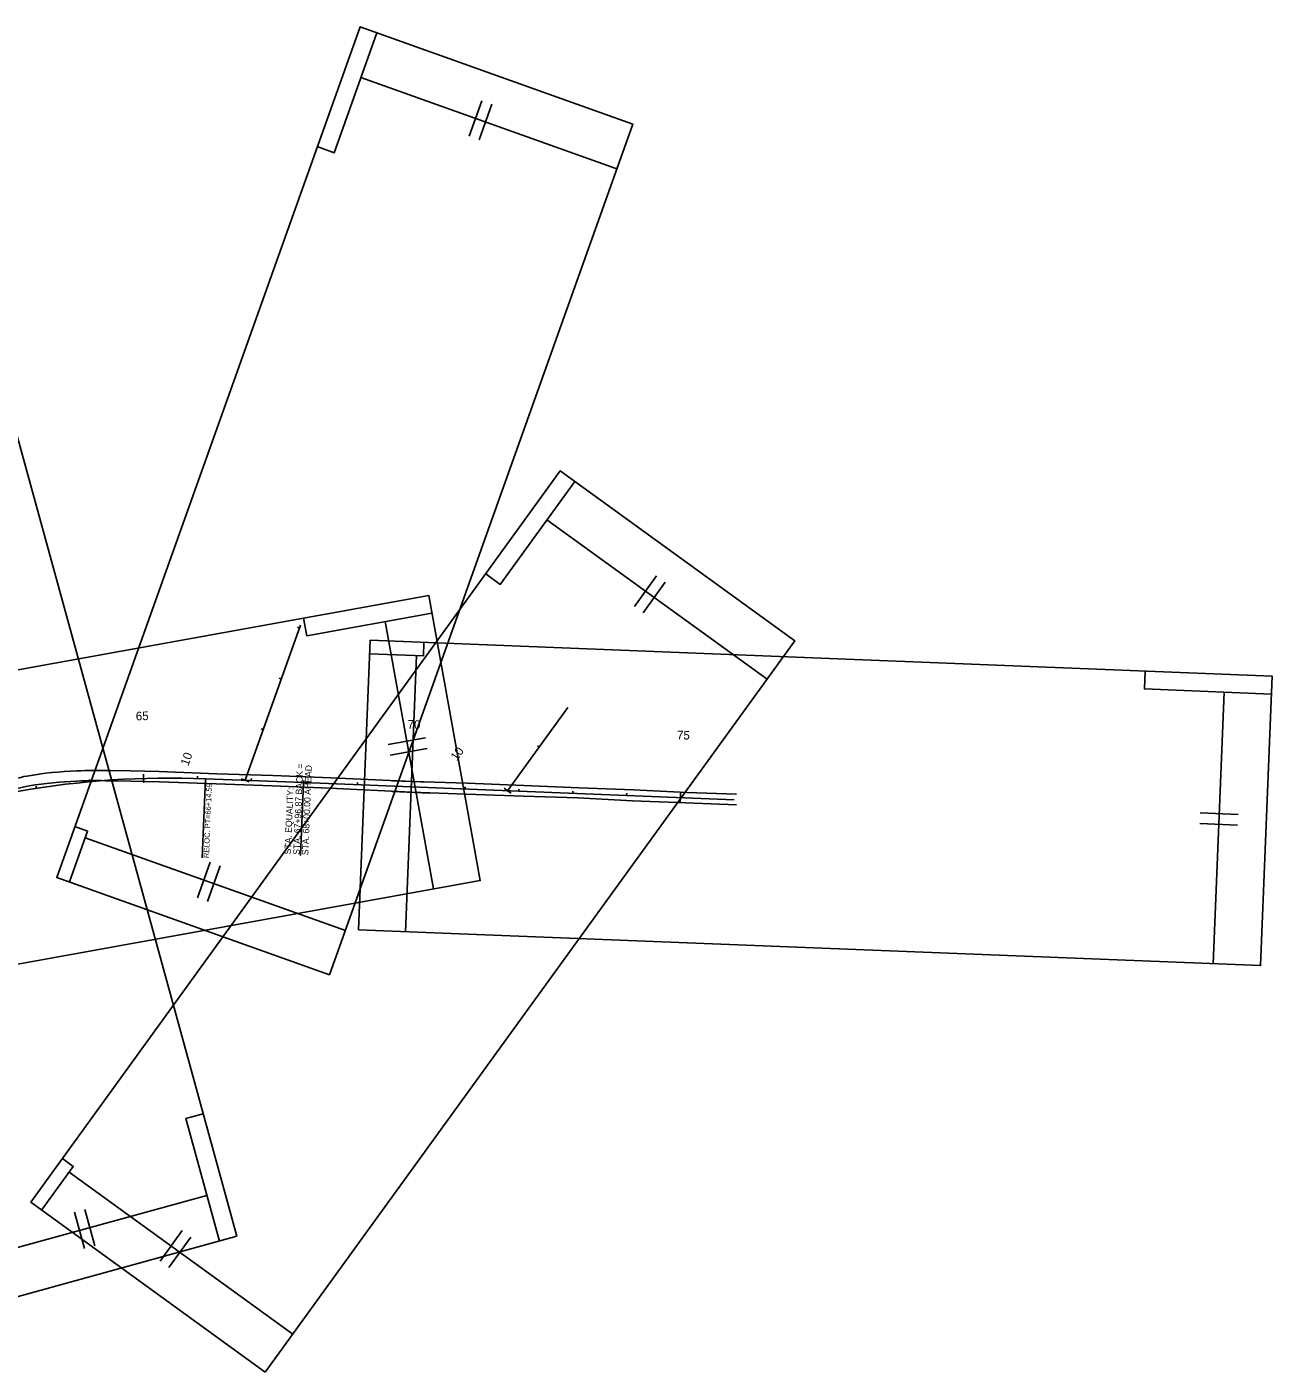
# Model space of a CAD drawing. Extents: x 1965658 to 1970277, y 1116791 to 1119319.
# Drawn here: x 1967966 to 1970277, y 1116823 to 1119319 of the extents above; entities that cross this region are included whole.
import ezdxf

# ---------------------------------------------------------------- set-up
doc = ezdxf.new("R2010")
doc.units = 0
for name, color, linetype in [('RD_EX_Road', 7, 'Continuous'), ('RD_HC_CL', 7, 'Continuous'), ('RD_HC_CL_Rel', 7, 'Continuous'), ('RD_HC_Data_Rel', 7, 'Continuous'), ('RD_HC_Data_Tic', 7, 'Continuous'), ('RD_HC_Data_Tic_Rel', 7, 'Continuous'), ('RD_HC_TX_Rel_Sta50', 7, 'Continuous'), ('RD_HC_TX_Sta50', 7, 'Continuous'), ('RD_SHT_Bndy', 7, 'Continuous')]:
    doc.layers.add(name, color=color, linetype=linetype)

msp = doc.modelspace()

# ---------------------------------------------------------------- linework, layer by layer
at = {"layer": 'RD_EX_Road'}
for points in [[(1968120.7, 1117939.2), (1968158.7, 1117938.6), (1968212.1, 1117937.2), (1968318.8, 1117933.3), (1968422.8, 1117929.9), (1968530.5, 1117925.7)], [(1968530.5, 1117925.7), (1968682, 1117919), (1968783.2, 1117915.4), (1968888.6, 1117911.4), (1968991.2, 1117907.1), (1969092, 1117903.1), (1969191.1, 1117898.7), (1969283.3, 1117895.4)], [(1968119.9, 1117920.1), (1968159.2, 1117919.4), (1968212.5, 1117918), (1968317.5, 1117914.4), (1968421.5, 1117910.8), (1968527.8, 1117906.4)], [(1968527.8, 1117906.4), (1968680.8, 1117899.1), (1968781.7, 1117895.4), (1968887.9, 1117891.8), (1968988.7, 1117888.2), (1969090.1, 1117882.8), (1969189.3, 1117879), (1969282.9, 1117875.4)]]:
    msp.add_lwpolyline(points, dxfattribs=at)
for centre, radius, start, end in [((1968104.9, 1117261.1), 682.1, 101.7162, 109.6396), ((1968075.1, 1117320.6), 617.9, 91.4965, 100.1295), ((1968100.4, 1117116.1), 823.4, 88.5878, 92.8836), ((1968081.5, 1117359.5), 562.4, 101.3634, 110.7161), ((1968080.7, 1117246.5), 673.3, 91.837, 99.4057), ((1968097.6, 1117060.1), 860.3, 88.5163, 92.5646)]:
    msp.add_arc(centre, radius, start, end, dxfattribs=at)
at = {"layer": 'RD_HC_CL'}
for p, q in [((1968371.4, 1117921), (1968474, 1118208.6)), ((1968858.2, 1117901.7), (1968970.1, 1118056.2))]:
    msp.add_line(p, q, dxfattribs=at)
at = {"layer": 'RD_HC_CL_Rel'}
for p, q in [((1968297.5, 1117923.9), (1968479.6, 1117916.7)), ((1968479.6, 1117916.7), (1969279, 1117884.9))]:
    msp.add_line(p, q, dxfattribs=at)
msp.add_arc((1968232.6, 1116288.2), 1637, 87.7266, 111.9958, dxfattribs=at)
at = {"layer": 'RD_HC_Data_Rel'}
for p, q in [((1968297.5, 1117923.9), (1968291.7, 1117777.2)), ((1968479.6, 1117916.7), (1968474.3, 1117781.6))]:
    msp.add_line(p, q, dxfattribs=at)
at = {"layer": 'RD_HC_Data_Tic'}
for p, q in [((1968472.1, 1118203.5), (1968468.4, 1118204.9)), ((1968438.5, 1118109.4), (1968434.8, 1118110.7)), ((1968404.9, 1118015.2), (1968401.2, 1118016.5)), ((1968916.8, 1117982.6), (1968913.6, 1117985)), ((1968371.4, 1117921), (1968363.8, 1117923.7)), ((1968371.4, 1117921), (1968378.9, 1117918.3)), ((1968858.2, 1117901.7), (1968851.7, 1117906.3)), ((1968858.2, 1117901.7), (1968864.7, 1117897))]:
    msp.add_line(p, q, dxfattribs=at)
at = {"layer": 'RD_HC_Data_Tic_Rel'}
for p, q in [((1968182.9, 1117924.4), (1968182.7, 1117932.4)), ((1968282.9, 1117924.4), (1968283, 1117928.4)), ((1967983.9, 1117906.2), (1967983.3, 1117910.2)), ((1968083.1, 1117918.4), (1968082.8, 1117922.3)), ((1968182.9, 1117924.4), (1968183.2, 1117916.5)), ((1968382.8, 1117920.5), (1968383, 1117924.5)), ((1968479.6, 1117916.7), (1968479.8, 1117920.7)), ((1968579.6, 1117912.7), (1968579.7, 1117916.7)), ((1968679.5, 1117908.7), (1968679.2, 1117900.8)), ((1968679.5, 1117908.7), (1968679.8, 1117916.7)), ((1968779.4, 1117904.8), (1968779.6, 1117908.8)), ((1968879.3, 1117900.8), (1968879.5, 1117904.8)), ((1968979.3, 1117896.8), (1968979.4, 1117900.8)), ((1969079.2, 1117892.9), (1969079.3, 1117896.9)), ((1969179.1, 1117888.9), (1969178.8, 1117880.9)), ((1969179.1, 1117888.9), (1969179.4, 1117896.9))]:
    msp.add_line(p, q, dxfattribs=at)
at = {"layer": 'RD_SHT_Bndy'}
for p, q in [((1969061.2, 1119055.1), (1968586.2, 1119224.6)), ((1968786.9, 1119115.8), (1968810.4, 1119181.7)), ((1968805.7, 1119109.1), (1968829.3, 1119175)), ((1969339.8, 1118108.4), (1968931.4, 1118404.3)), ((1969093.6, 1118243.6), (1969134.6, 1118300.3)), ((1969109.7, 1118231.9), (1969150.8, 1118288.5)), ((1968721.1, 1117719.4), (1968631.3, 1118215.7)), ((1968668.8, 1117640.2), (1968689.2, 1118152.3)), ((1970167.6, 1117580.7), (1970187.7, 1118084.6)), ((1968637, 1117987.5), (1968705.9, 1117999.9)), ((1968640.6, 1117967.8), (1968709.4, 1117980.3)), ((1968644.9, 1117920.1), (1968714.9, 1117917.4)), ((1968644.1, 1117900.1), (1968714.1, 1117897.4)), ((1970143.7, 1117860.6), (1970213.7, 1117857.8)), ((1970142.9, 1117840.6), (1970212.9, 1117837.9)), ((1968557.3, 1117642.3), (1968074.6, 1117814.5)), ((1968283, 1117703), (1968306.5, 1117768.9)), ((1968301.8, 1117696.3), (1968325.3, 1117762.2)), ((1968459.8, 1116893.7), (1968044.8, 1117194.4)), ((1967814.2, 1117017.5), (1968300.5, 1117151.1)), ((1968054.5, 1117119.8), (1968073, 1117052.3)), ((1968073.8, 1117125.1), (1968092.3, 1117057.6)), ((1968213.5, 1117028.9), (1968254.6, 1117085.6)), ((1968229.7, 1117017.1), (1968270.8, 1117073.8))]:
    msp.add_line(p, q, dxfattribs=at)
for points in [[(1968528.1, 1117560.4), (1969090.8, 1119138), (1968584.5, 1119318.6), (1968021.8, 1117740.9)], [(1967393.8, 1118547.8), (1967837.6, 1116932.6), (1968355.8, 1117075.1), (1967912, 1118690.2)], [(1968408.7, 1116823.2), (1969391.5, 1118179.7), (1968956.2, 1118495), (1967973.5, 1117138.6)], [(1967159.4, 1117436.9), (1968807.6, 1117735.1), (1968712, 1118264), (1967063.7, 1117965.8)], [(1968581.9, 1117643.7), (1970255.6, 1117577.2), (1970276.9, 1118114.3), (1968603.2, 1118180.7)]]:
    msp.add_lwpolyline(points, close=True, dxfattribs=at)
for points in [[(1968505.3, 1119096.5), (1968536.6, 1119085.3), (1968615.8, 1119307.4)], [(1968817.8, 1118304), (1968844.7, 1118284.5), (1968983.1, 1118475.5)], [(1968479.9, 1118222), (1968485.8, 1118189.3), (1968717.9, 1118231.3)], [(1968602.3, 1118155.8), (1968702.2, 1118151.8), (1968703.2, 1118176.8)], [(1970041.2, 1118123.6), (1970039.9, 1118090.5), (1970275.6, 1118081.1)], [(1968045.4, 1117732.6), (1968079, 1117826.8), (1968055.4, 1117835.2)], [(1968293.4, 1117302.5), (1968261.3, 1117293.7), (1968323.8, 1117066.3)], [(1967993.7, 1117123.9), (1968052.4, 1117204.9), (1968032.2, 1117219.6)]]:
    msp.add_lwpolyline(points, dxfattribs=at)

# ---------------------------------------------------------------- texts
at = {"layer": 'RD_HC_Data_Rel'}
for s, height, p in [('STA. 67+96.87 BACK =', 12, (1968472.5, 1117782.6)), ('STA. 68+00.00 AHEAD', 12, (1968488.6, 1117782)), ('RELOC. PT=66+14.59', 10, (1968304.2, 1117776.5)), ('STA. EQUALITY:', 12, (1968456.3, 1117783.3))]:
    msp.add_text(s, height=height, rotation=87.7266, dxfattribs=at).set_placement(p)
at = {"layer": 'RD_HC_TX_Rel_Sta50'}
for s, rotation, p in [('65', 1.7374, (1968168.7, 1118032.1)), ('70', 357.7266, (1968672.5, 1118017.1)), ('75', 357.7266, (1969172.4, 1117997.3))]:
    msp.add_text(s, height=16, rotation=rotation, dxfattribs=at).set_placement(p)
at = {"layer": 'RD_HC_TX_Sta50'}
for rotation, p in [(54.0772, (1968764.2, 1117956)), (70.3698, (1968265.9, 1117946.8))]:
    msp.add_text('10', height=16, rotation=rotation, dxfattribs=at).set_placement(p)

doc.saveas('drawing.dxf')
